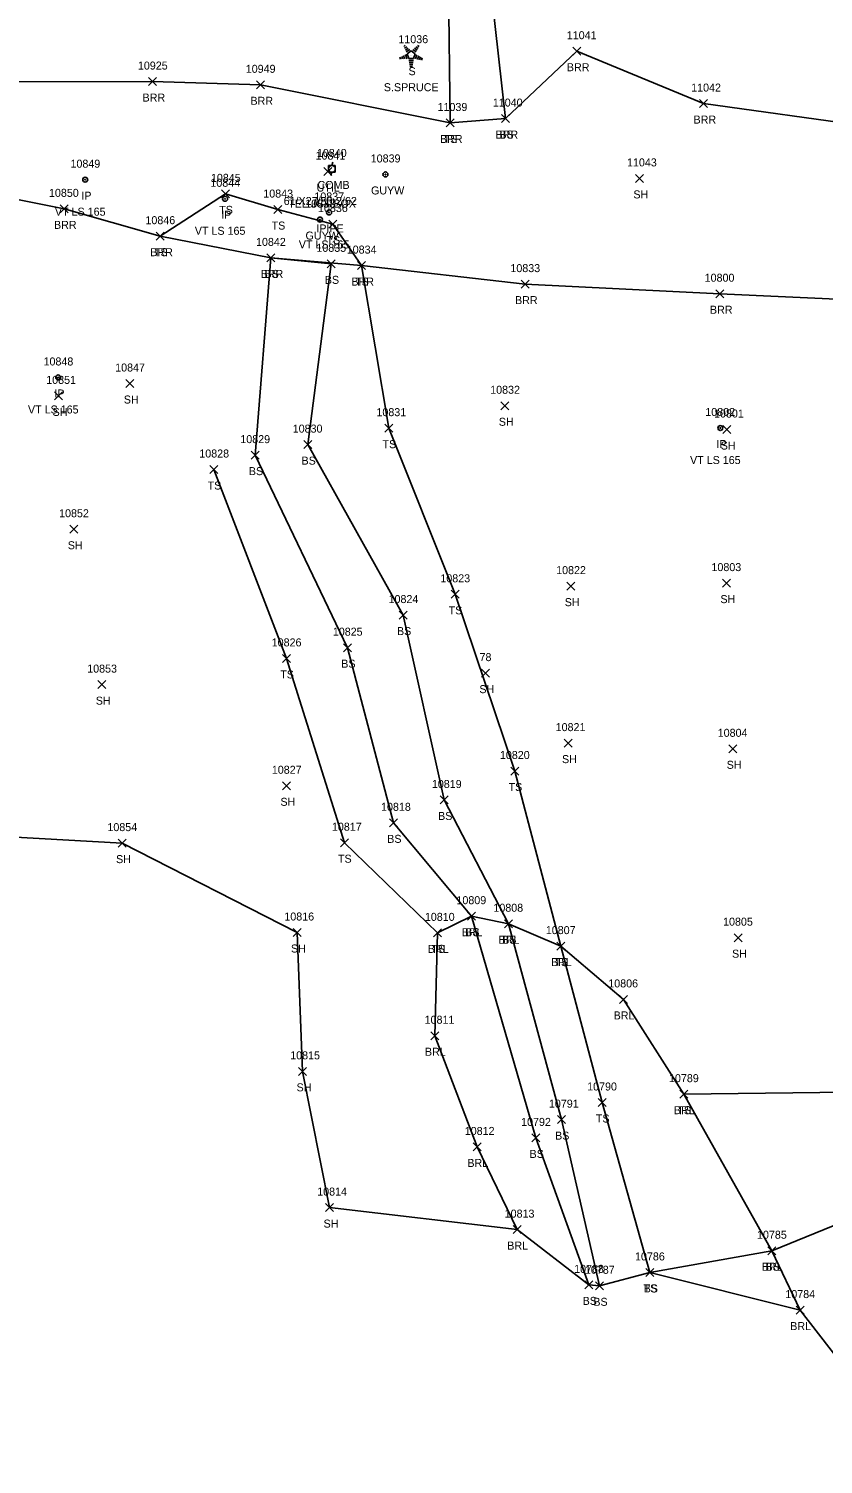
# Model space of a CAD drawing. Extents: x 1482574 to 1485769, y 580696 to 595649.
# Drawn here: x 1483303.5 to 1483502, y 582556.6 to 582915.4 of the extents above; entities that cross this region are included whole.
import ezdxf

# ---------------------------------------------------------------- set-up
doc = ezdxf.new("R2010")
doc.units = 0
for name, color, linetype in [('L_A', 7, 'Continuous'), ('L_C', 7, 'Continuous'), ('L_I', 7, 'Continuous'), ('L_TIC', 7, 'Continuous'), ('LABL', 7, 'Continuous'), ('LELB', 7, 'Continuous'), ('LSOGP', 7, 'Continuous'), ('LTC', 7, 'Continuous'), ('M_A', 7, 'Continuous'), ('M_C', 7, 'Continuous'), ('M_I', 7, 'Continuous'), ('MPIP', 7, 'Continuous'), ('MPIR', 7, 'Continuous'), ('U_A', 7, 'Continuous'), ('U_C', 7, 'Continuous'), ('U_I', 7, 'Continuous'), ('UDEFAULT', 7, 'Continuous'), ('UP', 7, 'Continuous'), ('UPGW', 7, 'Continuous')]:
    doc.layers.add(name, color=color, linetype=linetype)

msp = doc.modelspace()

# ---------------------------------------------------------------- linework, layer by layer
at = {"layer": 'L_TIC'}
for points in [[(1483439.45, 582908.76), (1483441.45, 582910.76)], [(1483441.45, 582908.76), (1483439.45, 582910.76)], [(1483333.43, 582901.17), (1483335.43, 582903.17)], [(1483335.43, 582901.17), (1483333.43, 582903.17)], [(1483360.39, 582900.36), (1483362.39, 582902.36)], [(1483362.39, 582900.36), (1483360.39, 582902.36)], [(1483471.1, 582895.67), (1483473.1, 582897.67)], [(1483473.1, 582895.67), (1483471.1, 582897.67)], [(1483407.74, 582890.82), (1483409.74, 582892.82)], [(1483409.74, 582890.82), (1483407.74, 582892.82)], [(1483407.74, 582890.82), (1483409.74, 582892.82)], [(1483409.74, 582890.82), (1483407.74, 582892.82)], [(1483421.63, 582891.92), (1483423.63, 582893.92)], [(1483423.63, 582891.92), (1483421.63, 582893.92)], [(1483421.63, 582891.92), (1483423.63, 582893.92)], [(1483423.63, 582891.92), (1483421.63, 582893.92)], [(1483455.07, 582876.97), (1483457.07, 582878.97)], [(1483457.07, 582876.97), (1483455.07, 582878.97)], [(1483351.67, 582873.11), (1483353.67, 582875.11)], [(1483353.67, 582873.11), (1483351.67, 582875.11)], [(1483311.3, 582869.36), (1483313.3, 582871.36)], [(1483313.3, 582869.36), (1483311.3, 582871.36)], [(1483364.76, 582869.18), (1483366.76, 582871.18)], [(1483366.76, 582869.18), (1483364.76, 582871.18)], [(1483378.48, 582865.56), (1483380.48, 582867.56)], [(1483380.48, 582865.56), (1483378.48, 582867.56)], [(1483335.36, 582862.53), (1483337.36, 582864.53)], [(1483337.36, 582862.53), (1483335.36, 582864.53)], [(1483335.36, 582862.53), (1483337.36, 582864.53)], [(1483337.36, 582862.53), (1483335.36, 582864.53)], [(1483335.36, 582862.53), (1483337.36, 582864.53)], [(1483337.36, 582862.53), (1483335.36, 582864.53)], [(1483362.94, 582857.1), (1483364.94, 582859.1)], [(1483364.94, 582857.1), (1483362.94, 582859.1)], [(1483362.94, 582857.1), (1483364.94, 582859.1)], [(1483364.94, 582857.1), (1483362.94, 582859.1)], [(1483362.94, 582857.1), (1483364.94, 582859.1)], [(1483364.94, 582857.1), (1483362.94, 582859.1)], [(1483378.02, 582855.62), (1483380.02, 582857.62)], [(1483380.02, 582855.62), (1483378.02, 582857.62)], [(1483385.61, 582855.18), (1483387.61, 582857.18)], [(1483387.61, 582855.18), (1483385.61, 582857.18)], [(1483385.61, 582855.18), (1483387.61, 582857.18)], [(1483387.61, 582855.18), (1483385.61, 582857.18)], [(1483426.5, 582850.55), (1483428.5, 582852.55)], [(1483428.5, 582850.55), (1483426.5, 582852.55)], [(1483475.2, 582848.15), (1483477.2, 582850.15)], [(1483477.2, 582848.15), (1483475.2, 582850.15)], [(1483327.75, 582825.71), (1483329.75, 582827.71)], [(1483329.75, 582825.71), (1483327.75, 582827.71)], [(1483309.95, 582822.62), (1483311.95, 582824.62)], [(1483311.95, 582822.62), (1483309.95, 582824.62)], [(1483421.45, 582820.15), (1483423.45, 582822.15)], [(1483423.45, 582820.15), (1483421.45, 582822.15)], [(1483392.46, 582814.55), (1483394.46, 582816.55)], [(1483394.46, 582814.55), (1483392.46, 582816.55)], [(1483476.9, 582814.21), (1483478.9, 582816.21)], [(1483478.9, 582814.21), (1483476.9, 582816.21)], [(1483359.03, 582807.81), (1483361.03, 582809.81)], [(1483361.03, 582807.81), (1483359.03, 582809.81)], [(1483372.2, 582810.44), (1483374.2, 582812.44)], [(1483374.2, 582810.44), (1483372.2, 582812.44)], [(1483348.77, 582804.22), (1483350.77, 582806.22)], [(1483350.77, 582804.22), (1483348.77, 582806.22)], [(1483313.74, 582789.29), (1483315.74, 582791.29)], [(1483315.74, 582789.29), (1483313.74, 582791.29)], [(1483437.92, 582775.07), (1483439.92, 582777.07)], [(1483439.92, 582775.07), (1483437.92, 582777.07)], [(1483476.82, 582775.83), (1483478.82, 582777.83)], [(1483478.82, 582775.83), (1483476.82, 582777.83)], [(1483409, 582773.03), (1483411, 582775.03)], [(1483411, 582773.03), (1483409, 582775.03)], [(1483396.06, 582767.84), (1483398.06, 582769.84)], [(1483398.06, 582767.84), (1483396.06, 582769.84)], [(1483366.92, 582757.01), (1483368.92, 582759.01)], [(1483368.92, 582757.01), (1483366.92, 582759.01)], [(1483382.13, 582759.69), (1483384.13, 582761.69)], [(1483384.13, 582759.69), (1483382.13, 582761.69)], [(1483416.58, 582753.33), (1483418.58, 582755.33)], [(1483418.58, 582753.33), (1483416.58, 582755.33)], [(1483320.76, 582750.46), (1483322.76, 582752.46)], [(1483322.76, 582750.46), (1483320.76, 582752.46)], [(1483437.24, 582735.84), (1483439.24, 582737.84)], [(1483439.24, 582735.84), (1483437.24, 582737.84)], [(1483478.38, 582734.42), (1483480.38, 582736.42)], [(1483480.38, 582734.42), (1483478.38, 582736.42)], [(1483423.97, 582728.87), (1483425.97, 582730.87)], [(1483425.97, 582728.87), (1483423.97, 582730.87)], [(1483366.89, 582725.18), (1483368.89, 582727.18)], [(1483368.89, 582725.18), (1483366.89, 582727.18)], [(1483406.32, 582721.63), (1483408.32, 582723.63)], [(1483408.32, 582721.63), (1483406.32, 582723.63)], [(1483393.62, 582715.92), (1483395.62, 582717.92)], [(1483395.62, 582715.92), (1483393.62, 582717.92)], [(1483325.81, 582710.85), (1483327.81, 582712.85)], [(1483327.81, 582710.85), (1483325.81, 582712.85)], [(1483381.34, 582710.95), (1483383.34, 582712.95)], [(1483383.34, 582710.95), (1483381.34, 582712.95)], [(1483413.1, 582692.59), (1483415.1, 582694.59)], [(1483415.1, 582692.59), (1483413.1, 582694.59)], [(1483413.1, 582692.59), (1483415.1, 582694.59)], [(1483415.1, 582692.59), (1483413.1, 582694.59)], [(1483369.51, 582688.51), (1483371.51, 582690.51)], [(1483371.51, 582688.51), (1483369.51, 582690.51)], [(1483422.33, 582690.7), (1483424.33, 582692.7)], [(1483424.33, 582690.7), (1483422.33, 582692.7)], [(1483422.33, 582690.7), (1483424.33, 582692.7)], [(1483424.33, 582690.7), (1483422.33, 582692.7)], [(1483404.65, 582688.42), (1483406.65, 582690.42)], [(1483406.65, 582688.42), (1483404.65, 582690.42)], [(1483404.65, 582688.42), (1483406.65, 582690.42)], [(1483406.65, 582688.42), (1483404.65, 582690.42)], [(1483435.43, 582685.11), (1483437.43, 582687.11)], [(1483437.43, 582685.11), (1483435.43, 582687.11)], [(1483435.43, 582685.11), (1483437.43, 582687.11)], [(1483437.43, 582685.11), (1483435.43, 582687.11)], [(1483479.72, 582687.22), (1483481.72, 582689.22)], [(1483481.72, 582687.22), (1483479.72, 582689.22)], [(1483451.09, 582671.79), (1483453.09, 582673.79)], [(1483453.09, 582671.79), (1483451.09, 582673.79)], [(1483403.93, 582662.71), (1483405.93, 582664.71)], [(1483405.93, 582662.71), (1483403.93, 582664.71)], [(1483370.92, 582653.81), (1483372.92, 582655.81)], [(1483372.92, 582653.81), (1483370.92, 582655.81)], [(1483445.77, 582646.03), (1483447.77, 582648.03)], [(1483447.77, 582646.03), (1483445.77, 582648.03)], [(1483466.14, 582648.11), (1483468.14, 582650.11)], [(1483468.14, 582648.11), (1483466.14, 582650.11)], [(1483466.14, 582648.11), (1483468.14, 582650.11)], [(1483468.14, 582648.11), (1483466.14, 582650.11)], [(1483435.56, 582641.74), (1483437.56, 582643.74)], [(1483437.56, 582641.74), (1483435.56, 582643.74)], [(1483414.53, 582634.92), (1483416.53, 582636.92)], [(1483416.53, 582634.92), (1483414.53, 582636.92)], [(1483429.18, 582637.18), (1483431.18, 582639.18)], [(1483431.18, 582637.18), (1483429.18, 582639.18)], [(1483377.67, 582619.77), (1483379.67, 582621.77)], [(1483379.67, 582619.77), (1483377.67, 582621.77)], [(1483424.51, 582614.26), (1483426.51, 582616.26)], [(1483426.51, 582614.26), (1483424.51, 582616.26)], [(1483488.12, 582608.98), (1483490.12, 582610.98)], [(1483490.12, 582608.98), (1483488.12, 582610.98)], [(1483488.12, 582608.98), (1483490.12, 582610.98)], [(1483490.12, 582608.98), (1483488.12, 582610.98)], [(1483457.69, 582603.56), (1483459.69, 582605.56)], [(1483459.69, 582603.56), (1483457.69, 582605.56)], [(1483457.69, 582603.56), (1483459.69, 582605.56)], [(1483459.69, 582603.56), (1483457.69, 582605.56)], [(1483442.43, 582600.45), (1483444.43, 582602.45)], [(1483444.43, 582600.45), (1483442.43, 582602.45)], [(1483445.12, 582600.22), (1483447.12, 582602.22)], [(1483447.12, 582600.22), (1483445.12, 582602.22)], [(1483495.2, 582594.15), (1483497.2, 582596.15)], [(1483497.2, 582594.15), (1483495.2, 582596.15)]]:
    msp.add_lwpolyline(points, dxfattribs=at)
at = {"layer": 'LABL'}
for points in [[(1483294.58, 582902.08), (1483334.43, 582902.17), (1483361.39, 582901.36), (1483408.74, 582891.82), (1483422.63, 582892.92), (1483440.45, 582909.76), (1483472.1, 582896.67), (1483512.82, 582891.05), (1483577.57, 582895.54), (1483642.96, 582897.05), (1483689.36, 582892.83), (1483750.76, 582888.62), (1483798.36, 582883.23), (1483823.86, 582883.53), (1483871.2, 582884.65), (1483912.08, 582881.62), (1483947.92, 582878.18)], [(1484185.41, 582815.52), (1484140.59, 582824.65), (1484098.11, 582828.5), (1484067.01, 582831.11), (1484018.35, 582825.16), (1483990.34, 582825.07), (1483953.63, 582826.22), (1483931.61, 582825.29), (1483914.53, 582829.45), (1483872.69, 582831.09), (1483825.63, 582836.26), (1483775.6, 582836.04), (1483722.62, 582839.3), (1483673.01, 582838.16), (1483630.1, 582838.66), (1483577.84, 582841.83), (1483529.01, 582846.71), (1483476.2, 582849.15), (1483427.5, 582851.55), (1483386.61, 582856.18), (1483363.94, 582858.1), (1483336.36, 582863.53), (1483312.3, 582870.36), (1483288.9, 582875.06)], [(1483496.2, 582595.15), (1483489.12, 582609.98), (1483467.14, 582649.11), (1483452.09, 582672.79), (1483436.43, 582686.11), (1483423.33, 582691.7), (1483414.1, 582693.59), (1483405.65, 582689.42), (1483404.93, 582663.71), (1483415.53, 582635.92), (1483425.51, 582615.26)]]:
    msp.add_lwpolyline(points, dxfattribs=at)
at = {"layer": 'LELB'}
for points in [[(1483348.01, 582929.89), (1483376.23, 582945.6), (1483392.89, 582968.38), (1483403.47, 582997.44), (1483420.63, 583035.83), (1483423.07, 583058.28), (1483422.03, 583072.12), (1483431.62, 583067.98), (1483444.85, 583055.35), (1483433.41, 583036.33), (1483421.34, 583001.16), (1483411.74, 582955.95), (1483408.35, 582926.23), (1483408.74, 582891.82)], [(1483445.36, 583060.65), (1483444.27, 583036.99), (1483434.48, 582998.14), (1483423.83, 582957.68), (1483419.07, 582924.16), (1483422.63, 582892.92)], [(1483458.69, 582604.56), (1483446.77, 582647.03), (1483436.43, 582686.11), (1483424.97, 582729.87), (1483410, 582774.03), (1483393.46, 582815.55), (1483386.61, 582856.18), (1483379.48, 582866.56), (1483365.76, 582870.18), (1483352.67, 582874.11), (1483336.36, 582863.53)], [(1483443.43, 582601.45), (1483430.18, 582638.18), (1483414.1, 582693.59), (1483394.62, 582716.92), (1483383.13, 582760.69), (1483360.03, 582808.81), (1483363.94, 582858.1)], [(1483446.12, 582601.22), (1483436.56, 582642.74), (1483423.33, 582691.7), (1483407.32, 582722.63), (1483397.06, 582768.84), (1483373.2, 582811.44), (1483379.02, 582856.62), (1483363.94, 582858.1)], [(1483405.65, 582689.42), (1483382.34, 582711.95), (1483367.92, 582758.01), (1483349.77, 582805.22)], [(1483712.89, 582625.78), (1483665.64, 582641.91), (1483617.39, 582646.73), (1483569.2, 582650.36), (1483467.14, 582649.11)], [(1483712.89, 582625.78), (1483665.49, 582623.16), (1483615.86, 582624.66), (1483571.82, 582619.81), (1483510.84, 582618.8), (1483489.12, 582609.98), (1483458.69, 582604.56)]]:
    msp.add_lwpolyline(points, dxfattribs=at)
at = {"layer": 'LSOGP'}
msp.add_lwpolyline([(1483735.88, 582562.73), (1483697.48, 582561.06), (1483663.51, 582559.84), (1483650.02, 582556.61), (1483626.37, 582559.53), (1483591.62, 582560.95), (1483549.59, 582563.94), (1483513.73, 582572.58), (1483496.2, 582595.15), (1483458.69, 582604.56), (1483446.12, 582601.22), (1483443.43, 582601.45), (1483425.51, 582615.26), (1483378.67, 582620.77), (1483371.92, 582654.81), (1483370.51, 582689.51), (1483326.81, 582711.85), (1483277.87, 582714.55)], dxfattribs=at)
at = {"layer": 'LTC'}
for p, q in [((1483397.19, 582910.97), (1483397.54, 582911.23)), ((1483397.4, 582910.51), (1483397.93, 582910.89)), ((1483397.61, 582910.04), (1483398.31, 582910.55)), ((1483397.82, 582909.58), (1483398.7, 582910.21)), ((1483398.04, 582909.12), (1483399.06, 582909.86)), ((1483399.06, 582909.86), (1483400.05, 582909.13)), ((1483399.48, 582910.17), (1483400.28, 582909.58)), ((1483399.85, 582910.52), (1483400.53, 582910.02)), ((1483400.22, 582910.86), (1483400.77, 582910.47)), ((1483400.59, 582911.21), (1483401.01, 582910.91)), ((1483396.22, 582908.25), (1483396.37, 582907.78)), ((1483396.68, 582908.47), (1483396.89, 582907.82)), ((1483397.13, 582908.69), (1483397.4, 582907.85)), ((1483397.59, 582908.9), (1483397.92, 582907.88)), ((1483398.04, 582909.12), (1483398.43, 582907.93)), ((1483399.66, 582907.93), (1483398.43, 582907.93)), ((1483399.62, 582907.43), (1483398.48, 582907.43)), ((1483399.54, 582906.93), (1483398.55, 582906.93)), ((1483399.46, 582906.43), (1483398.62, 582906.43)), ((1483399.37, 582905.93), (1483398.7, 582905.93)), ((1483400.05, 582909.13), (1483399.66, 582907.93)), ((1483400.49, 582908.86), (1483400.15, 582907.82)), ((1483400.93, 582908.61), (1483400.65, 582907.72)), ((1483401.38, 582908.36), (1483401.14, 582907.63)), ((1483401.82, 582908.11), (1483401.64, 582907.53))]:
    msp.add_line(p, q, dxfattribs=at)
at = {"layer": 'MPIP'}
for radius in [0.625, 0.0833]:
    msp.add_circle((1483378.52, 582869.46), radius, dxfattribs=at)
at = {"layer": 'MPIR'}
for centre, radius in [((1483317.59, 582877.65), 0.625), ((1483317.59, 582877.65), 0.0833), ((1483352.54, 582872.88), 0.625), ((1483352.54, 582872.88), 0.0833), ((1483310.84, 582828.22), 0.625), ((1483310.84, 582828.22), 0.0833), ((1483476.28, 582815.59), 0.625), ((1483476.28, 582815.59), 0.0833)]:
    msp.add_circle(centre, radius, dxfattribs=at)
at = {"layer": 'UDEFAULT'}
for points in [[(1483377.25, 582878.67), (1483379.25, 582880.67)], [(1483379.25, 582878.67), (1483377.25, 582880.67)]]:
    msp.add_lwpolyline(points, dxfattribs=at)
at = {"layer": 'UP'}
for p, q in [((1483378.41, 582879.49), (1483378.41, 582881.16)), ((1483378.41, 582881.16), (1483380.08, 582881.16)), ((1483379.49, 582881.99), (1483379.24, 582881.16)), ((1483380.08, 582881.16), (1483380.08, 582879.49)), ((1483380.08, 582879.49), (1483378.41, 582879.49)), ((1483378.99, 582878.66), (1483379.24, 582879.49)), ((1483379.24, 582880.33), (1483379.24, 582880.33))]:
    msp.add_line(p, q, dxfattribs=at)
msp.add_circle((1483379.24, 582880.33), 0.833, dxfattribs=at)
at = {"layer": 'UPGW'}
for centre, radius in [((1483392.61, 582878.96), 0.625), ((1483392.61, 582878.96), 0.0833), ((1483376.25, 582867.68), 0.625), ((1483376.25, 582867.68), 0.0833)]:
    msp.add_circle(centre, radius, dxfattribs=at)

# ---------------------------------------------------------------- texts
at = {"layer": 'L_A'}
for s, p in [('S', (1483398.38, 582903.76)), ('BRR', (1483437.94, 582904.76)), ('BRR', (1483331.92, 582897.17)), ('BRR', (1483358.88, 582896.36)), ('BRR', (1483469.59, 582891.67)), ('BRR', (1483406.23, 582886.82)), ('TS', (1483407.15, 582886.82)), ('BRR', (1483420.11, 582887.92)), ('BS', (1483421.07, 582887.92)), ('SH', (1483454.56, 582872.97)), ('TS', (1483351.08, 582869.11)), ('BRR', (1483309.79, 582865.36)), ('TS', (1483364.17, 582865.18)), ('TS', (1483377.89, 582861.56)), ('BRR', (1483333.85, 582858.53)), ('TS', (1483334.77, 582858.53)), ('TS', (1483334.77, 582858.53)), ('BRR', (1483361.43, 582853.1)), ('BS', (1483362.38, 582853.1)), ('BS', (1483362.38, 582853.1)), ('BS', (1483377.46, 582851.62)), ('BRR', (1483384.1, 582851.18)), ('TS', (1483385.02, 582851.18)), ('BRR', (1483424.99, 582846.55)), ('BRR', (1483473.69, 582844.15)), ('SH', (1483327.24, 582821.71)), ('SH', (1483309.44, 582818.62)), ('SH', (1483420.94, 582816.15)), ('TS', (1483391.87, 582810.55)), ('SH', (1483476.38, 582810.21)), ('BS', (1483358.47, 582803.81)), ('BS', (1483371.64, 582806.44)), ('TS', (1483348.18, 582800.22)), ('SH', (1483313.23, 582785.29)), ('SH', (1483437.41, 582771.07)), ('SH', (1483476.31, 582771.83)), ('TS', (1483408.41, 582769.03)), ('BS', (1483395.5, 582763.84)), ('BS', (1483381.57, 582755.69)), ('TS', (1483366.33, 582753.01)), ('SH', (1483320.24, 582746.46)), ('SH', (1483416.07, 582749.33)), ('SH', (1483436.73, 582731.84)), ('SH', (1483477.87, 582730.42)), ('TS', (1483423.38, 582724.87)), ('SH', (1483366.38, 582721.18)), ('BS', (1483405.76, 582717.63)), ('BS', (1483393.06, 582711.92)), ('SH', (1483325.3, 582706.85)), ('TS', (1483380.75, 582706.95)), ('BRL', (1483411.65, 582688.59)), ('BS', (1483412.54, 582688.59)), ('BRL', (1483420.87, 582686.7)), ('BS', (1483421.77, 582686.7)), ('SH', (1483369, 582684.51)), ('BRL', (1483403.2, 582684.42)), ('TS', (1483404.06, 582684.42)), ('SH', (1483479.21, 582683.22)), ('BRL', (1483433.97, 582681.11)), ('TS', (1483434.84, 582681.11)), ('BRL', (1483449.63, 582667.79)), ('BRL', (1483402.48, 582658.71)), ('SH', (1483370.4, 582649.81)), ('TS', (1483445.18, 582642.03)), ('BRL', (1483464.68, 582644.11)), ('TS', (1483465.55, 582644.11)), ('BS', (1483435, 582637.74)), ('BS', (1483428.62, 582633.18)), ('BRL', (1483413.08, 582630.92)), ('SH', (1483377.15, 582615.77)), ('BRL', (1483423.05, 582610.26)), ('BRL', (1483486.66, 582604.98)), ('BS', (1483487.56, 582604.98)), ('TS', (1483457.1, 582599.56)), ('BS', (1483457.13, 582599.56)), ('BS', (1483441.88, 582596.45)), ('BS', (1483444.56, 582596.22)), ('BRL', (1483493.74, 582590.15))]:
    msp.add_text(s, height=2, dxfattribs=at).set_placement(p)
at = {"layer": 'L_C'}
msp.add_text('S.SPRUCE', height=2, dxfattribs=at).set_placement((1483392.21, 582899.76))
at = {"layer": 'L_I'}
for s, p in [('11036', (1483395.84, 582911.76)), ('11041', (1483437.92, 582912.76)), ('10925', (1483330.76, 582905.17)), ('10949', (1483357.71, 582904.36)), ('11042', (1483469, 582899.67)), ('11039', (1483405.63, 582894.82)), ('11039', (1483405.63, 582894.82)), ('11040', (1483419.44, 582895.92)), ('11040', (1483419.44, 582895.92)), ('11043', (1483452.97, 582880.97)), ('10845', (1483349, 582877.11)), ('10850', (1483308.54, 582873.36)), ('10843', (1483362.09, 582873.18)), ('10836', (1483375.76, 582869.56)), ('10846', (1483332.64, 582866.53)), ('10846', (1483332.64, 582866.53)), ('10846', (1483332.64, 582866.53)), ('10842', (1483360.27, 582861.1)), ('10842', (1483360.27, 582861.1)), ('10842', (1483360.27, 582861.1)), ('10835', (1483375.35, 582859.62)), ('10834', (1483382.94, 582859.18)), ('10834', (1483382.94, 582859.18)), ('10833', (1483423.83, 582854.55)), ('10800', (1483472.37, 582852.15)), ('10847', (1483325.08, 582829.71)), ('10851', (1483307.85, 582826.62)), ('10832', (1483418.78, 582824.15)), ('10831', (1483390.36, 582818.55)), ('10801', (1483474.71, 582818.21)), ('10830', (1483369.44, 582814.44)), ('10829', (1483356.35, 582811.81)), ('10828', (1483346.1, 582808.22)), ('10852', (1483311.07, 582793.29)), ('10822', (1483435.26, 582779.07)), ('10803', (1483474.07, 582779.83)), ('10823', (1483406.33, 582777.03)), ('10824', (1483393.39, 582771.84)), ('10826', (1483364.19, 582761.01)), ('10825', (1483379.46, 582763.69)), ('78', (1483416.12, 582757.33)), ('10853', (1483318.09, 582754.46)), ('10821', (1483435.14, 582739.84)), ('10804', (1483475.63, 582738.42)), ('10820', (1483421.21, 582732.87)), ('10827', (1483364.22, 582729.18)), ('10819', (1483404.21, 582725.63)), ('10818', (1483391.51, 582719.92)), ('10854', (1483323.14, 582714.85)), ('10817', (1483379.24, 582714.95)), ('10809', (1483410.35, 582696.59)), ('10809', (1483410.35, 582696.59)), ('10816', (1483367.35, 582692.51)), ('10810', (1483402.46, 582692.42)), ('10810', (1483402.46, 582692.42)), ('10808', (1483419.58, 582694.7)), ('10808', (1483419.58, 582694.7)), ('10807', (1483432.68, 582689.11)), ('10807', (1483432.68, 582689.11)), ('10805', (1483476.97, 582691.22)), ('10806', (1483448.29, 582675.79)), ('10811', (1483402.4, 582666.71)), ('10815', (1483368.81, 582657.81)), ('10790', (1483443.01, 582650.03)), ('10789', (1483463.46, 582652.11)), ('10789', (1483463.46, 582652.11)), ('10791', (1483433.46, 582645.74)), ('10812', (1483412.43, 582638.92)), ('10792', (1483426.51, 582641.18)), ('10814', (1483375.56, 582623.77)), ('10813', (1483422.4, 582618.26)), ('10785', (1483485.45, 582612.98)), ('10785', (1483485.45, 582612.98)), ('10786', (1483454.97, 582607.56)), ('10786', (1483454.97, 582607.56)), ('10788', (1483439.76, 582604.45)), ('10787', (1483442.45, 582604.22)), ('10784', (1483492.53, 582598.15))]:
    msp.add_text(s, height=2, dxfattribs=at).set_placement(p)
at = {"layer": 'LTC'}
msp.add_text('.', height=1.04, rotation=270, dxfattribs=at).set_placement((1483398.94, 582908.87))
at = {"layer": 'M_A'}
for s, p in [('IP', (1483316.63, 582872.65)), ('IP', (1483351.59, 582867.88)), ('IPIPE', (1483375.35, 582864.46)), ('IP', (1483309.89, 582823.22)), ('IP', (1483475.33, 582810.59))]:
    msp.add_text(s, height=2, dxfattribs=at).set_placement(p)
at = {"layer": 'M_C'}
for p in [(1483310.03, 582868.65), (1483344.98, 582863.88), (1483370.96, 582860.46), (1483303.29, 582819.22), (1483468.72, 582806.59)]:
    msp.add_text('VT LS 165', height=2, dxfattribs=at).set_placement(p)
at = {"layer": 'M_I'}
for s, p in [('10849', (1483313.91, 582880.65)), ('10844', (1483348.87, 582875.88)), ('10837', (1483374.85, 582872.46)), ('10848', (1483307.18, 582831.22)), ('10802', (1483472.53, 582818.59))]:
    msp.add_text(s, height=2, dxfattribs=at).set_placement(p)
at = {"layer": 'U_A'}
for s, p in [('COMB', (1483375.63, 582875.33)), ('UTIL', (1483375.41, 582874.67)), ('GUYW', (1483389, 582873.96)), ('GUYW', (1483372.64, 582862.68))]:
    msp.add_text(s, height=2, dxfattribs=at).set_placement(p)
at = {"layer": 'U_C'}
for s, p in [('61/X27/50-2/62', (1483367.18, 582871.33)), ('TEL JCT BOX', (1483368.31, 582870.67))]:
    msp.add_text(s, height=2, dxfattribs=at).set_placement(p)
at = {"layer": 'U_I'}
for s, p in [('10841', (1483375.15, 582882.67)), ('10840', (1483375.49, 582883.33)), ('10839', (1483388.93, 582881.96)), ('10838', (1483372.58, 582870.68))]:
    msp.add_text(s, height=2, dxfattribs=at).set_placement(p)

doc.saveas('drawing.dxf')
